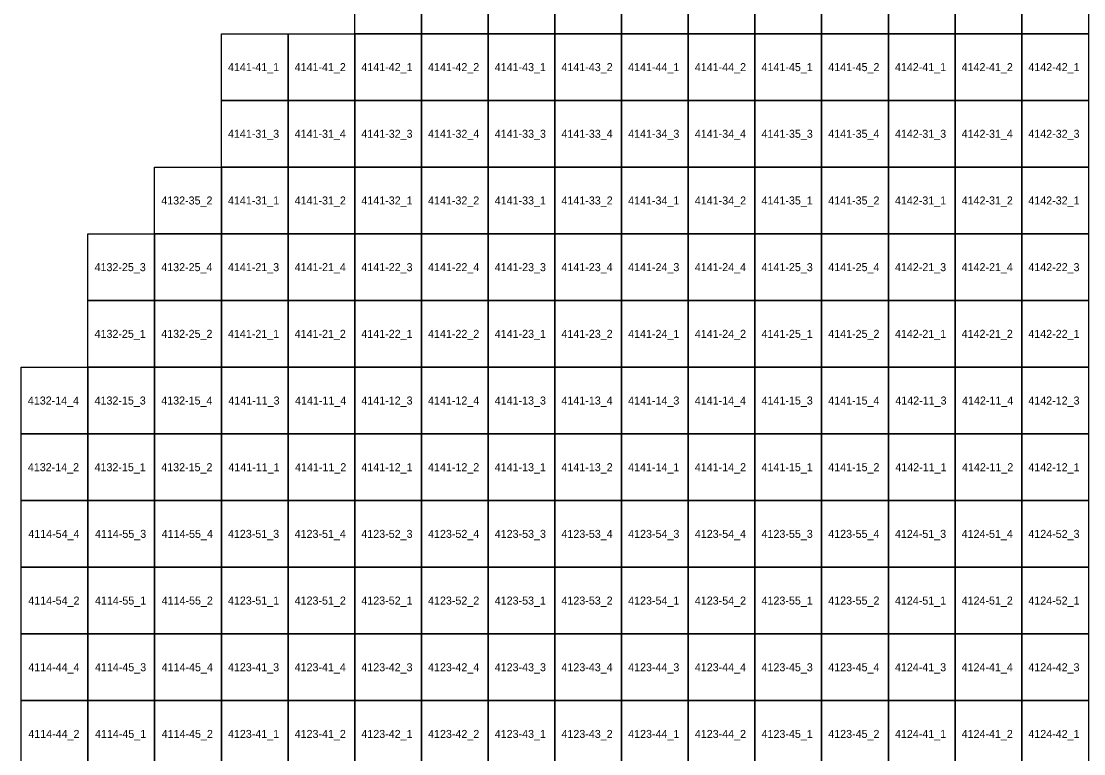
# Model space of a CAD drawing. Extents: x 312500 to 765000, y 172500 to 440000.
# Drawn here: x 342500 to 382325, y 340507 to 367970 of the extents above; entities that cross this region are included whole.
import ezdxf

# ---------------------------------------------------------------- set-up
doc = ezdxf.new("R2010")
doc.units = 0
doc.layers.add('Topo5_ramis_TKS2025', color=7, linetype='Continuous')
doc.layers.add('Topo5_ramis_TKS2025_Nr', color=7, linetype='Continuous')

msp = doc.modelspace()

# ---------------------------------------------------------------- linework, layer by layer
at = {"layer": 'Topo5_ramis_TKS2025'}
for points in [[(355000, 367500), (355000, 370000), (357500, 370000), (357500, 367500), (355000, 367500)], [(357500, 367500), (357500, 370000), (360000, 370000), (360000, 367500), (357500, 367500)], [(360000, 367500), (360000, 370000), (362500, 370000), (362500, 367500), (360000, 367500)], [(362500, 367500), (362500, 370000), (365000, 370000), (365000, 367500), (362500, 367500)], [(365000, 367500), (365000, 370000), (367500, 370000), (367500, 367500), (365000, 367500)], [(367500, 367500), (367500, 370000), (370000, 370000), (370000, 367500), (367500, 367500)], [(370000, 367500), (370000, 370000), (372500, 370000), (372500, 367500), (370000, 367500)], [(372500, 367500), (372500, 370000), (375000, 370000), (375000, 367500), (372500, 367500)], [(375000, 367500), (375000, 370000), (377500, 370000), (377500, 367500), (375000, 367500)], [(377500, 367500), (377500, 370000), (380000, 370000), (380000, 367500), (377500, 367500)], [(380000, 367500), (380000, 370000), (382500, 370000), (382500, 367500), (380000, 367500)], [(350000, 365000), (350000, 367500), (352500, 367500), (352500, 365000), (350000, 365000)], [(352500, 365000), (352500, 367500), (355000, 367500), (355000, 365000), (352500, 365000)], [(355000, 365000), (355000, 367500), (357500, 367500), (357500, 365000), (355000, 365000)], [(357500, 365000), (357500, 367500), (360000, 367500), (360000, 365000), (357500, 365000)], [(360000, 365000), (360000, 367500), (362500, 367500), (362500, 365000), (360000, 365000)], [(362500, 365000), (362500, 367500), (365000, 367500), (365000, 365000), (362500, 365000)], [(365000, 365000), (365000, 367500), (367500, 367500), (367500, 365000), (365000, 365000)], [(367500, 365000), (367500, 367500), (370000, 367500), (370000, 365000), (367500, 365000)], [(370000, 365000), (370000, 367500), (372500, 367500), (372500, 365000), (370000, 365000)], [(372500, 365000), (372500, 367500), (375000, 367500), (375000, 365000), (372500, 365000)], [(375000, 365000), (375000, 367500), (377500, 367500), (377500, 365000), (375000, 365000)], [(377500, 365000), (377500, 367500), (380000, 367500), (380000, 365000), (377500, 365000)], [(380000, 365000), (380000, 367500), (382500, 367500), (382500, 365000), (380000, 365000)], [(350000, 362500), (350000, 365000), (352500, 365000), (352500, 362500), (350000, 362500)], [(352500, 362500), (352500, 365000), (355000, 365000), (355000, 362500), (352500, 362500)], [(355000, 362500), (355000, 365000), (357500, 365000), (357500, 362500), (355000, 362500)], [(357500, 362500), (357500, 365000), (360000, 365000), (360000, 362500), (357500, 362500)], [(360000, 362500), (360000, 365000), (362500, 365000), (362500, 362500), (360000, 362500)], [(362500, 362500), (362500, 365000), (365000, 365000), (365000, 362500), (362500, 362500)], [(365000, 362500), (365000, 365000), (367500, 365000), (367500, 362500), (365000, 362500)], [(367500, 362500), (367500, 365000), (370000, 365000), (370000, 362500), (367500, 362500)], [(370000, 362500), (370000, 365000), (372500, 365000), (372500, 362500), (370000, 362500)], [(372500, 362500), (372500, 365000), (375000, 365000), (375000, 362500), (372500, 362500)], [(375000, 362500), (375000, 365000), (377500, 365000), (377500, 362500), (375000, 362500)], [(377500, 362500), (377500, 365000), (380000, 365000), (380000, 362500), (377500, 362500)], [(380000, 362500), (380000, 365000), (382500, 365000), (382500, 362500), (380000, 362500)], [(347500, 360000), (347500, 362500), (350000, 362500), (350000, 360000), (347500, 360000)], [(350000, 360000), (350000, 362500), (352500, 362500), (352500, 360000), (350000, 360000)], [(352500, 360000), (352500, 362500), (355000, 362500), (355000, 360000), (352500, 360000)], [(355000, 360000), (355000, 362500), (357500, 362500), (357500, 360000), (355000, 360000)], [(357500, 360000), (357500, 362500), (360000, 362500), (360000, 360000), (357500, 360000)], [(360000, 360000), (360000, 362500), (362500, 362500), (362500, 360000), (360000, 360000)], [(362500, 360000), (362500, 362500), (365000, 362500), (365000, 360000), (362500, 360000)], [(365000, 360000), (365000, 362500), (367500, 362500), (367500, 360000), (365000, 360000)], [(367500, 360000), (367500, 362500), (370000, 362500), (370000, 360000), (367500, 360000)], [(370000, 360000), (370000, 362500), (372500, 362500), (372500, 360000), (370000, 360000)], [(372500, 360000), (372500, 362500), (375000, 362500), (375000, 360000), (372500, 360000)], [(375000, 360000), (375000, 362500), (377500, 362500), (377500, 360000), (375000, 360000)], [(377500, 360000), (377500, 362500), (380000, 362500), (380000, 360000), (377500, 360000)], [(380000, 360000), (380000, 362500), (382500, 362500), (382500, 360000), (380000, 360000)], [(345000, 357500), (345000, 360000), (347500, 360000), (347500, 357500), (345000, 357500)], [(347500, 357500), (347500, 360000), (350000, 360000), (350000, 357500), (347500, 357500)], [(350000, 357500), (350000, 360000), (352500, 360000), (352500, 357500), (350000, 357500)], [(352500, 357500), (352500, 360000), (355000, 360000), (355000, 357500), (352500, 357500)], [(355000, 357500), (355000, 360000), (357500, 360000), (357500, 357500), (355000, 357500)], [(357500, 357500), (357500, 360000), (360000, 360000), (360000, 357500), (357500, 357500)], [(360000, 357500), (360000, 360000), (362500, 360000), (362500, 357500), (360000, 357500)], [(362500, 357500), (362500, 360000), (365000, 360000), (365000, 357500), (362500, 357500)], [(365000, 357500), (365000, 360000), (367500, 360000), (367500, 357500), (365000, 357500)], [(367500, 357500), (367500, 360000), (370000, 360000), (370000, 357500), (367500, 357500)], [(370000, 357500), (370000, 360000), (372500, 360000), (372500, 357500), (370000, 357500)], [(372500, 357500), (372500, 360000), (375000, 360000), (375000, 357500), (372500, 357500)], [(375000, 357500), (375000, 360000), (377500, 360000), (377500, 357500), (375000, 357500)], [(377500, 357500), (377500, 360000), (380000, 360000), (380000, 357500), (377500, 357500)], [(380000, 357500), (380000, 360000), (382500, 360000), (382500, 357500), (380000, 357500)], [(345000, 355000), (345000, 357500), (347500, 357500), (347500, 355000), (345000, 355000)], [(347500, 355000), (347500, 357500), (350000, 357500), (350000, 355000), (347500, 355000)], [(350000, 355000), (350000, 357500), (352500, 357500), (352500, 355000), (350000, 355000)], [(352500, 355000), (352500, 357500), (355000, 357500), (355000, 355000), (352500, 355000)], [(355000, 355000), (355000, 357500), (357500, 357500), (357500, 355000), (355000, 355000)], [(357500, 355000), (357500, 357500), (360000, 357500), (360000, 355000), (357500, 355000)], [(360000, 355000), (360000, 357500), (362500, 357500), (362500, 355000), (360000, 355000)], [(362500, 355000), (362500, 357500), (365000, 357500), (365000, 355000), (362500, 355000)], [(365000, 355000), (365000, 357500), (367500, 357500), (367500, 355000), (365000, 355000)], [(367500, 355000), (367500, 357500), (370000, 357500), (370000, 355000), (367500, 355000)], [(370000, 355000), (370000, 357500), (372500, 357500), (372500, 355000), (370000, 355000)], [(372500, 355000), (372500, 357500), (375000, 357500), (375000, 355000), (372500, 355000)], [(375000, 355000), (375000, 357500), (377500, 357500), (377500, 355000), (375000, 355000)], [(377500, 355000), (377500, 357500), (380000, 357500), (380000, 355000), (377500, 355000)], [(380000, 355000), (380000, 357500), (382500, 357500), (382500, 355000), (380000, 355000)], [(342500, 352500), (342500, 355000), (345000, 355000), (345000, 352500), (342500, 352500)], [(345000, 352500), (345000, 355000), (347500, 355000), (347500, 352500), (345000, 352500)], [(347500, 352500), (347500, 355000), (350000, 355000), (350000, 352500), (347500, 352500)], [(350000, 352500), (350000, 355000), (352500, 355000), (352500, 352500), (350000, 352500)], [(352500, 352500), (352500, 355000), (355000, 355000), (355000, 352500), (352500, 352500)], [(355000, 352500), (355000, 355000), (357500, 355000), (357500, 352500), (355000, 352500)], [(357500, 352500), (357500, 355000), (360000, 355000), (360000, 352500), (357500, 352500)], [(360000, 352500), (360000, 355000), (362500, 355000), (362500, 352500), (360000, 352500)], [(362500, 352500), (362500, 355000), (365000, 355000), (365000, 352500), (362500, 352500)], [(365000, 352500), (365000, 355000), (367500, 355000), (367500, 352500), (365000, 352500)], [(367500, 352500), (367500, 355000), (370000, 355000), (370000, 352500), (367500, 352500)], [(370000, 352500), (370000, 355000), (372500, 355000), (372500, 352500), (370000, 352500)], [(372500, 352500), (372500, 355000), (375000, 355000), (375000, 352500), (372500, 352500)], [(375000, 352500), (375000, 355000), (377500, 355000), (377500, 352500), (375000, 352500)], [(377500, 352500), (377500, 355000), (380000, 355000), (380000, 352500), (377500, 352500)], [(380000, 352500), (380000, 355000), (382500, 355000), (382500, 352500), (380000, 352500)], [(342500, 350000), (342500, 352500), (345000, 352500), (345000, 350000), (342500, 350000)], [(345000, 350000), (345000, 352500), (347500, 352500), (347500, 350000), (345000, 350000)], [(347500, 350000), (347500, 352500), (350000, 352500), (350000, 350000), (347500, 350000)], [(350000, 350000), (350000, 352500), (352500, 352500), (352500, 350000), (350000, 350000)], [(352500, 350000), (352500, 352500), (355000, 352500), (355000, 350000), (352500, 350000)], [(355000, 350000), (355000, 352500), (357500, 352500), (357500, 350000), (355000, 350000)], [(357500, 350000), (357500, 352500), (360000, 352500), (360000, 350000), (357500, 350000)], [(360000, 350000), (360000, 352500), (362500, 352500), (362500, 350000), (360000, 350000)], [(362500, 350000), (362500, 352500), (365000, 352500), (365000, 350000), (362500, 350000)], [(365000, 350000), (365000, 352500), (367500, 352500), (367500, 350000), (365000, 350000)], [(367500, 350000), (367500, 352500), (370000, 352500), (370000, 350000), (367500, 350000)], [(370000, 350000), (370000, 352500), (372500, 352500), (372500, 350000), (370000, 350000)], [(372500, 350000), (372500, 352500), (375000, 352500), (375000, 350000), (372500, 350000)], [(375000, 350000), (375000, 352500), (377500, 352500), (377500, 350000), (375000, 350000)], [(377500, 350000), (377500, 352500), (380000, 352500), (380000, 350000), (377500, 350000)], [(380000, 350000), (380000, 352500), (382500, 352500), (382500, 350000), (380000, 350000)], [(342500, 347500), (342500, 350000), (345000, 350000), (345000, 347500), (342500, 347500)], [(345000, 347500), (345000, 350000), (347500, 350000), (347500, 347500), (345000, 347500)], [(347500, 347500), (347500, 350000), (350000, 350000), (350000, 347500), (347500, 347500)], [(350000, 347500), (350000, 350000), (352500, 350000), (352500, 347500), (350000, 347500)], [(352500, 347500), (352500, 350000), (355000, 350000), (355000, 347500), (352500, 347500)], [(355000, 347500), (355000, 350000), (357500, 350000), (357500, 347500), (355000, 347500)], [(357500, 347500), (357500, 350000), (360000, 350000), (360000, 347500), (357500, 347500)], [(360000, 347500), (360000, 350000), (362500, 350000), (362500, 347500), (360000, 347500)], [(362500, 347500), (362500, 350000), (365000, 350000), (365000, 347500), (362500, 347500)], [(365000, 347500), (365000, 350000), (367500, 350000), (367500, 347500), (365000, 347500)], [(367500, 347500), (367500, 350000), (370000, 350000), (370000, 347500), (367500, 347500)], [(370000, 347500), (370000, 350000), (372500, 350000), (372500, 347500), (370000, 347500)], [(372500, 347500), (372500, 350000), (375000, 350000), (375000, 347500), (372500, 347500)], [(375000, 347500), (375000, 350000), (377500, 350000), (377500, 347500), (375000, 347500)], [(377500, 347500), (377500, 350000), (380000, 350000), (380000, 347500), (377500, 347500)], [(380000, 347500), (380000, 350000), (382500, 350000), (382500, 347500), (380000, 347500)], [(342500, 345000), (342500, 347500), (345000, 347500), (345000, 345000), (342500, 345000)], [(345000, 345000), (345000, 347500), (347500, 347500), (347500, 345000), (345000, 345000)], [(347500, 345000), (347500, 347500), (350000, 347500), (350000, 345000), (347500, 345000)], [(350000, 345000), (350000, 347500), (352500, 347500), (352500, 345000), (350000, 345000)], [(352500, 345000), (352500, 347500), (355000, 347500), (355000, 345000), (352500, 345000)], [(355000, 345000), (355000, 347500), (357500, 347500), (357500, 345000), (355000, 345000)], [(357500, 345000), (357500, 347500), (360000, 347500), (360000, 345000), (357500, 345000)], [(360000, 345000), (360000, 347500), (362500, 347500), (362500, 345000), (360000, 345000)], [(362500, 345000), (362500, 347500), (365000, 347500), (365000, 345000), (362500, 345000)], [(365000, 345000), (365000, 347500), (367500, 347500), (367500, 345000), (365000, 345000)], [(367500, 345000), (367500, 347500), (370000, 347500), (370000, 345000), (367500, 345000)], [(370000, 345000), (370000, 347500), (372500, 347500), (372500, 345000), (370000, 345000)], [(372500, 345000), (372500, 347500), (375000, 347500), (375000, 345000), (372500, 345000)], [(375000, 345000), (375000, 347500), (377500, 347500), (377500, 345000), (375000, 345000)], [(377500, 345000), (377500, 347500), (380000, 347500), (380000, 345000), (377500, 345000)], [(380000, 345000), (380000, 347500), (382500, 347500), (382500, 345000), (380000, 345000)], [(342500, 342500), (342500, 345000), (345000, 345000), (345000, 342500), (342500, 342500)], [(345000, 342500), (345000, 345000), (347500, 345000), (347500, 342500), (345000, 342500)], [(347500, 342500), (347500, 345000), (350000, 345000), (350000, 342500), (347500, 342500)], [(350000, 342500), (350000, 345000), (352500, 345000), (352500, 342500), (350000, 342500)], [(352500, 342500), (352500, 345000), (355000, 345000), (355000, 342500), (352500, 342500)], [(355000, 342500), (355000, 345000), (357500, 345000), (357500, 342500), (355000, 342500)], [(357500, 342500), (357500, 345000), (360000, 345000), (360000, 342500), (357500, 342500)], [(360000, 342500), (360000, 345000), (362500, 345000), (362500, 342500), (360000, 342500)], [(362500, 342500), (362500, 345000), (365000, 345000), (365000, 342500), (362500, 342500)], [(365000, 342500), (365000, 345000), (367500, 345000), (367500, 342500), (365000, 342500)], [(367500, 342500), (367500, 345000), (370000, 345000), (370000, 342500), (367500, 342500)], [(370000, 342500), (370000, 345000), (372500, 345000), (372500, 342500), (370000, 342500)], [(372500, 342500), (372500, 345000), (375000, 345000), (375000, 342500), (372500, 342500)], [(375000, 342500), (375000, 345000), (377500, 345000), (377500, 342500), (375000, 342500)], [(377500, 342500), (377500, 345000), (380000, 345000), (380000, 342500), (377500, 342500)], [(380000, 342500), (380000, 345000), (382500, 345000), (382500, 342500), (380000, 342500)], [(342500, 340000), (342500, 342500), (345000, 342500), (345000, 340000), (342500, 340000)], [(345000, 340000), (345000, 342500), (347500, 342500), (347500, 340000), (345000, 340000)], [(347500, 340000), (347500, 342500), (350000, 342500), (350000, 340000), (347500, 340000)], [(350000, 340000), (350000, 342500), (352500, 342500), (352500, 340000), (350000, 340000)], [(352500, 340000), (352500, 342500), (355000, 342500), (355000, 340000), (352500, 340000)], [(355000, 340000), (355000, 342500), (357500, 342500), (357500, 340000), (355000, 340000)], [(357500, 340000), (357500, 342500), (360000, 342500), (360000, 340000), (357500, 340000)], [(360000, 340000), (360000, 342500), (362500, 342500), (362500, 340000), (360000, 340000)], [(362500, 340000), (362500, 342500), (365000, 342500), (365000, 340000), (362500, 340000)], [(365000, 340000), (365000, 342500), (367500, 342500), (367500, 340000), (365000, 340000)], [(367500, 340000), (367500, 342500), (370000, 342500), (370000, 340000), (367500, 340000)], [(370000, 340000), (370000, 342500), (372500, 342500), (372500, 340000), (370000, 340000)], [(372500, 340000), (372500, 342500), (375000, 342500), (375000, 340000), (372500, 340000)], [(375000, 340000), (375000, 342500), (377500, 342500), (377500, 340000), (375000, 340000)], [(377500, 340000), (377500, 342500), (380000, 342500), (380000, 340000), (377500, 340000)], [(380000, 340000), (380000, 342500), (382500, 342500), (382500, 340000), (380000, 340000)]]:
    msp.add_lwpolyline(points, dxfattribs=at)

# ---------------------------------------------------------------- texts
at = {"layer": 'Topo5_ramis_TKS2025_Nr'}
for s, p in [('4141-41_1', (350248, 366100)), ('4141-41_2', (352748, 366100)), ('4141-42_1', (355248, 366100)), ('4141-42_2', (357748, 366100)), ('4141-43_1', (360248, 366100)), ('4141-43_2', (362748, 366100)), ('4141-44_1', (365248, 366100)), ('4141-44_2', (367748, 366100)), ('4141-45_1', (370248, 366100)), ('4141-45_2', (372748, 366100)), ('4142-41_1', (375248, 366100)), ('4142-41_2', (377748, 366100)), ('4142-42_1', (380248, 366100)), ('4141-31_3', (350248, 363600)), ('4141-31_4', (352748, 363600)), ('4141-32_3', (355248, 363600)), ('4141-32_4', (357748, 363600)), ('4141-33_3', (360248, 363600)), ('4141-33_4', (362748, 363600)), ('4141-34_3', (365248, 363600)), ('4141-34_4', (367748, 363600)), ('4141-35_3', (370248, 363600)), ('4141-35_4', (372748, 363600)), ('4142-31_3', (375248, 363600)), ('4142-31_4', (377748, 363600)), ('4142-32_3', (380248, 363600)), ('4132-35_2', (347748, 361100)), ('4141-31_1', (350248, 361100)), ('4141-31_2', (352748, 361100)), ('4141-32_1', (355248, 361100)), ('4141-32_2', (357748, 361100)), ('4141-33_1', (360248, 361100)), ('4141-33_2', (362748, 361100)), ('4141-34_1', (365248, 361100)), ('4141-34_2', (367748, 361100)), ('4141-35_1', (370248, 361100)), ('4141-35_2', (372748, 361100)), ('4142-31_1', (375248, 361100)), ('4142-31_2', (377748, 361100)), ('4142-32_1', (380248, 361100)), ('4132-25_3', (345248, 358600)), ('4132-25_4', (347748, 358600)), ('4141-21_3', (350248, 358600)), ('4141-21_4', (352748, 358600)), ('4141-22_3', (355248, 358600)), ('4141-22_4', (357748, 358600)), ('4141-23_3', (360248, 358600)), ('4141-23_4', (362748, 358600)), ('4141-24_3', (365248, 358600)), ('4141-24_4', (367748, 358600)), ('4141-25_3', (370248, 358600)), ('4141-25_4', (372748, 358600)), ('4142-21_3', (375248, 358600)), ('4142-21_4', (377748, 358600)), ('4142-22_3', (380248, 358600)), ('4132-25_1', (345248, 356100)), ('4132-25_2', (347748, 356100)), ('4141-21_1', (350248, 356100)), ('4141-21_2', (352748, 356100)), ('4141-22_1', (355248, 356100)), ('4141-22_2', (357748, 356100)), ('4141-23_1', (360248, 356100)), ('4141-23_2', (362748, 356100)), ('4141-24_1', (365248, 356100)), ('4141-24_2', (367748, 356100)), ('4141-25_1', (370248, 356100)), ('4141-25_2', (372748, 356100)), ('4142-21_1', (375248, 356100)), ('4142-21_2', (377748, 356100)), ('4142-22_1', (380248, 356100)), ('4132-14_4', (342748, 353600)), ('4132-15_3', (345248, 353600)), ('4132-15_4', (347748, 353600)), ('4141-11_3', (350264, 353600)), ('4141-11_4', (352764, 353600)), ('4141-12_3', (355248, 353600)), ('4141-12_4', (357748, 353600)), ('4141-13_3', (360248, 353600)), ('4141-13_4', (362748, 353600)), ('4141-14_3', (365248, 353600)), ('4141-14_4', (367748, 353600)), ('4141-15_3', (370248, 353600)), ('4141-15_4', (372748, 353600)), ('4142-11_3', (375264, 353600)), ('4142-11_4', (377764, 353600)), ('4142-12_3', (380248, 353600)), ('4132-14_2', (342748, 351100)), ('4132-15_1', (345248, 351100)), ('4132-15_2', (347748, 351100)), ('4141-11_1', (350264, 351100)), ('4141-11_2', (352764, 351100)), ('4141-12_1', (355248, 351100)), ('4141-12_2', (357748, 351100)), ('4141-13_1', (360248, 351100)), ('4141-13_2', (362748, 351100)), ('4141-14_1', (365248, 351100)), ('4141-14_2', (367748, 351100)), ('4141-15_1', (370248, 351100)), ('4141-15_2', (372748, 351100)), ('4142-11_1', (375264, 351100)), ('4142-11_2', (377764, 351100)), ('4142-12_1', (380248, 351100)), ('4114-54_4', (342764, 348600)), ('4114-55_3', (345264, 348600)), ('4114-55_4', (347764, 348600)), ('4123-51_3', (350248, 348600)), ('4123-51_4', (352748, 348600)), ('4123-52_3', (355248, 348600)), ('4123-52_4', (357748, 348600)), ('4123-53_3', (360248, 348600)), ('4123-53_4', (362748, 348600)), ('4123-54_3', (365248, 348600)), ('4123-54_4', (367748, 348600)), ('4123-55_3', (370248, 348600)), ('4123-55_4', (372748, 348600)), ('4124-51_3', (375248, 348600)), ('4124-51_4', (377748, 348600)), ('4124-52_3', (380248, 348600)), ('4114-54_2', (342764, 346100)), ('4114-55_1', (345264, 346100)), ('4114-55_2', (347764, 346100)), ('4123-51_1', (350248, 346100)), ('4123-51_2', (352748, 346100)), ('4123-52_1', (355248, 346100)), ('4123-52_2', (357748, 346100)), ('4123-53_1', (360248, 346100)), ('4123-53_2', (362748, 346100)), ('4123-54_1', (365248, 346100)), ('4123-54_2', (367748, 346100)), ('4123-55_1', (370248, 346100)), ('4123-55_2', (372748, 346100)), ('4124-51_1', (375248, 346100)), ('4124-51_2', (377748, 346100)), ('4124-52_1', (380248, 346100)), ('4114-44_4', (342764, 343600)), ('4114-45_3', (345264, 343600)), ('4114-45_4', (347764, 343600)), ('4123-41_3', (350248, 343600)), ('4123-41_4', (352748, 343600)), ('4123-42_3', (355248, 343600)), ('4123-42_4', (357748, 343600)), ('4123-43_3', (360248, 343600)), ('4123-43_4', (362748, 343600)), ('4123-44_3', (365248, 343600)), ('4123-44_4', (367748, 343600)), ('4123-45_3', (370248, 343600)), ('4123-45_4', (372748, 343600)), ('4124-41_3', (375248, 343600)), ('4124-41_4', (377748, 343600)), ('4124-42_3', (380248, 343600)), ('4114-44_2', (342764, 341100)), ('4114-45_1', (345264, 341100)), ('4114-45_2', (347764, 341100)), ('4123-41_1', (350248, 341100)), ('4123-41_2', (352748, 341100)), ('4123-42_1', (355248, 341100)), ('4123-42_2', (357748, 341100)), ('4123-43_1', (360248, 341100)), ('4123-43_2', (362748, 341100)), ('4123-44_1', (365248, 341100)), ('4123-44_2', (367748, 341100)), ('4123-45_1', (370248, 341100)), ('4123-45_2', (372748, 341100)), ('4124-41_1', (375248, 341100)), ('4124-41_2', (377748, 341100)), ('4124-42_1', (380248, 341100))]:
    msp.add_text(s, height=300, dxfattribs=at).set_placement(p)

doc.saveas('drawing.dxf')
